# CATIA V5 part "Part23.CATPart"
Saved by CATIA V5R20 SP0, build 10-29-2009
Part number: VA 100812-3 - comprimido
Revision: ANY
Definition: UNKNOWN
Nomenclature: VA 100812-3 - comprimido
Source: Unknown
Bounding box of the stored display mesh (mm): x -3.1 to 3.1, y -0.003 to 4.7, z -3.1 to 3.1
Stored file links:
  C:\Users\Utente\Desktop\IO LAVORO\3D X SITO CF\CUMSA\3D files VA\VA 121012\Part23.CATPart
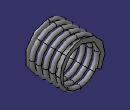
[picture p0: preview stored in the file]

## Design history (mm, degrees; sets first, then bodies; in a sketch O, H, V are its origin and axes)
Body1 "Cortar-Extruir2" (main body)
  Solid1: solid without history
